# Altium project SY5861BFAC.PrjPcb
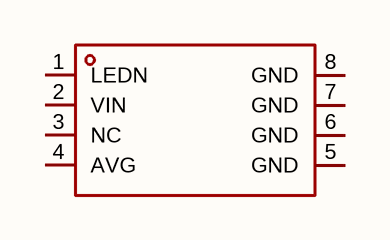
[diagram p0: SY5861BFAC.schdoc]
1 sheet, 1 parts. Net scope: global (net labels, ports and power ports of the same name join across sheets).

## Sheet SY5861BFAC.schdoc
size 127 x 101 mm

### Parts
U?  sy5861bfac  [SO-8_L4.9-W3.9-P1.27-LS5.9-BL]  (value not drawn)

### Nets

Not connected (* = marked no-connect by the designer): U? 1(LEDN) 2(VIN) 3(NC) 4(AVG) 5(GND) 6(GND) 7(GND) 8(GND)

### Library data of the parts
U? = sy5861bfac: 类型:-;工作电压(DC):-;开关频率:-;通道数:1;输出电压:20V~100V;输出电流:250mA;调光:-;拓扑结构:-;; Manufacturer: Silergy(矽力杰); AddInBom: yes; ModelId: 756fba4e187a48c69a2c935cd5c4465b; ModelName: SO-8_L4.9-W3.9-H1.5-LS5.9-P1.27; ModelTransform: 240.39054,192.913,0,270,0,0,0.0005,-0.0005,0; Number of Channels: 1; Output Current: 250mA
